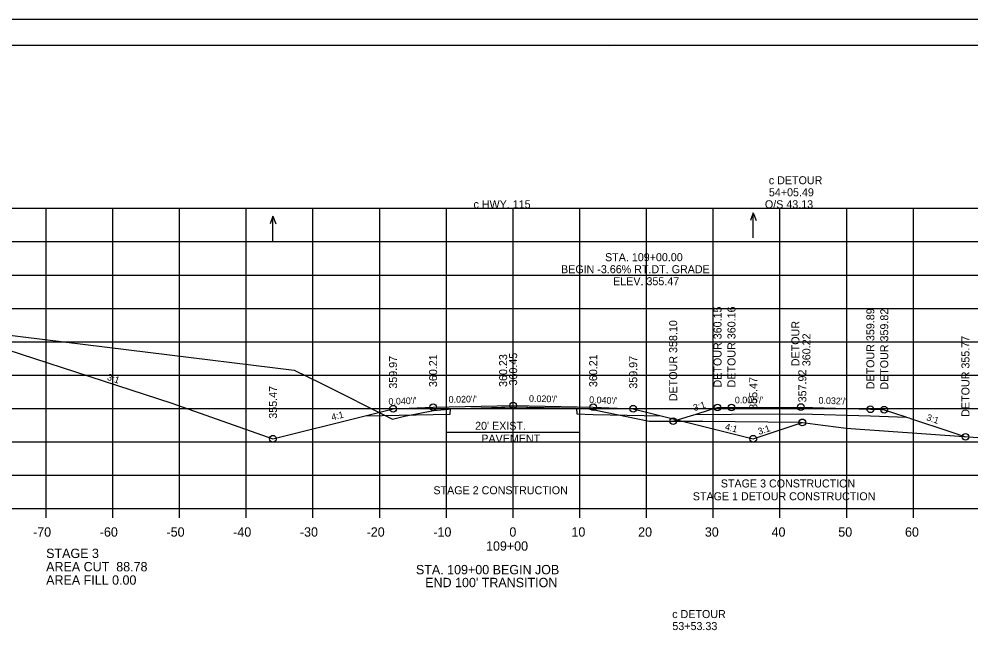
# Model space of a CAD drawing. Extents: x 1630712 to 1632516, y 782146 to 785403.
# Drawn here: x 1632258.9 to 1632401.6, y 783818.1 to 783910 of the extents above; entities that cross this region are included whole.
import ezdxf

# ---------------------------------------------------------------- set-up
doc = ezdxf.new("R2010")
doc.units = 0
for name, color, linetype in [('Notes', 7, 'Continuous'), ('R_Alt Surface', 7, 'Continuous'), ('R_Annot', 7, 'Continuous'), ('R_Axis', 7, 'Continuous'), ('R_Axis Annot', 7, 'Continuous'), ('R_Border', 7, 'Continuous'), ('R_Detour Subgrade', 7, 'Continuous'), ('R_Detour Surface', 7, 'Continuous'), ('R_Exist Surface', 7, 'Continuous'), ('R_Fin Surface', 7, 'Continuous'), ('R_Grid', 7, 'Continuous'), ('R_No Plot', 7, 'Continuous'), ('R_Water Annot', 7, 'Continuous'), ('R_Xsect Elev', 7, 'Continuous'), ('R_Xsect Elev Detour', 7, 'Continuous'), ('R_Xsect Slope', 7, 'Continuous')]:
    doc.layers.add(name, color=color, linetype=linetype)

msp = doc.modelspace()

# ---------------------------------------------------------------- linework, layer by layer
at = {"layer": 'Notes'}
for p, q in [((1632322.96, 783846.37), (1632322.96, 783849.77)), ((1632342.96, 783846.37), (1632342.96, 783849.77)), ((1632322.96, 783848.07), (1632342.96, 783848.07))]:
    msp.add_line(p, q, dxfattribs=at)
at = {"layer": 'R_Alt Surface'}
msp.add_lwpolyline([(1632310.79, 783850.54), (1632320.96, 783850.74), (1632323.5, 783850.79), (1632323.55, 783851.57), (1632332.75, 783851.85), (1632342.47, 783851.67), (1632342.52, 783850.8), (1632344.96, 783850.74), (1632355.14, 783850.54)], dxfattribs=at)
at = {"layer": 'R_Axis'}
for p, q in [((1632212.96, 783836.62), (1632492.96, 783836.62)), ((1632262.96, 783835.22), (1632262.96, 783836.62)), ((1632272.96, 783835.22), (1632272.96, 783836.62)), ((1632282.96, 783835.22), (1632282.96, 783836.62)), ((1632292.96, 783835.22), (1632292.96, 783836.62)), ((1632302.96, 783835.22), (1632302.96, 783836.62)), ((1632312.96, 783835.22), (1632312.96, 783836.62)), ((1632322.96, 783835.22), (1632322.96, 783836.62)), ((1632332.96, 783835.22), (1632332.96, 783836.62)), ((1632342.96, 783835.22), (1632342.96, 783836.62)), ((1632352.96, 783835.22), (1632352.96, 783836.62)), ((1632362.96, 783835.22), (1632362.96, 783836.62)), ((1632372.96, 783835.22), (1632372.96, 783836.62)), ((1632382.96, 783835.22), (1632382.96, 783836.62)), ((1632392.96, 783835.22), (1632392.96, 783836.62))]:
    msp.add_line(p, q, dxfattribs=at)
at = {"layer": 'R_Border'}
for p, q in [((1632194.96, 783906.08), (1632511.14, 783906.08)), ((1632347.48, 783905.82), (1632347.48, 783905.82)), ((1632347.48, 783905.82), (1632347.48, 783905.82))]:
    msp.add_line(p, q, dxfattribs=at)
at = {"layer": 'R_Detour Subgrade'}
msp.add_lwpolyline([(1632360.27, 783850.74), (1632365.69, 783850.78), (1632376.1, 783850.84), (1632386.51, 783850.5), (1632391.92, 783850.33)], dxfattribs=at)
at = {"layer": 'R_Detour Surface'}
msp.add_lwpolyline([(1632356.95, 783849.72), (1632359.72, 783850.57), (1632360.27, 783850.74), (1632362.56, 783851.45), (1632363.6, 783851.77), (1632364.8, 783851.77), (1632365.69, 783851.78), (1632376.1, 783851.84), (1632376.1, 783851.84), (1632376.1, 783851.84), (1632386.51, 783851.5), (1632388.05, 783851.45), (1632388.59, 783851.44), (1632391.82, 783850.36), (1632391.92, 783850.33), (1632391.93, 783850.32), (1632392.29, 783850.21), (1632392.54, 783850.12), (1632392.54, 783850.12), (1632398.58, 783848.11), (1632400.76, 783847.38)], dxfattribs=at)
at = {"layer": 'R_Exist Surface'}
msp.add_lwpolyline([(1632256.26, 783862.76), (1632300.13, 783857.36), (1632304.11, 783855.4), (1632314.86, 783850.04), (1632316.68, 783850.46), (1632321.04, 783851.33), (1632323.22, 783851.54), (1632323.55, 783851.57), (1632331.72, 783851.82), (1632332.75, 783851.85), (1632341.55, 783851.69), (1632342.47, 783851.67), (1632344.3, 783851.55), (1632344.76, 783851.52), (1632345.11, 783851.44), (1632353.35, 783849.74), (1632361.39, 783849.7), (1632375.97, 783849.58), (1632378.25, 783849.29), (1632382.87, 783848.65), (1632418.85, 783846.11)], dxfattribs=at)
at = {"layer": 'R_Fin Surface'}
msp.add_lwpolyline([(1632246.74, 783863.83), (1632281.81, 783852.44), (1632296.96, 783847.09), (1632310.79, 783850.54), (1632314.96, 783851.59), (1632320.96, 783851.83), (1632332.96, 783852.07), (1632344.96, 783851.83), (1632350.96, 783851.59), (1632355.14, 783850.54), (1632368.96, 783847.09), (1632368.96, 783847.09), (1632376.31, 783849.54)], dxfattribs=at)
at = {"layer": 'R_Grid'}
for p, q in [((1632212.96, 783881.62), (1632492.96, 783881.62)), ((1632262.96, 783836.62), (1632262.96, 783881.62)), ((1632272.96, 783836.62), (1632272.96, 783881.62)), ((1632282.96, 783836.62), (1632282.96, 783881.62)), ((1632292.96, 783836.62), (1632292.96, 783881.62)), ((1632302.96, 783836.62), (1632302.96, 783881.62)), ((1632312.96, 783836.62), (1632312.96, 783881.62)), ((1632322.96, 783836.62), (1632322.96, 783881.62)), ((1632332.96, 783836.62), (1632332.96, 783881.62)), ((1632342.96, 783836.62), (1632342.96, 783881.62)), ((1632352.96, 783836.62), (1632352.96, 783881.62)), ((1632362.96, 783836.62), (1632362.96, 783881.62)), ((1632372.96, 783836.62), (1632372.96, 783881.62)), ((1632382.96, 783836.62), (1632382.96, 783881.62)), ((1632392.96, 783836.62), (1632392.96, 783881.62)), ((1632212.96, 783876.62), (1632492.96, 783876.62)), ((1632212.96, 783871.62), (1632492.96, 783871.62)), ((1632212.96, 783866.62), (1632492.96, 783866.62)), ((1632212.96, 783861.62), (1632492.96, 783861.62)), ((1632212.96, 783856.62), (1632492.96, 783856.62)), ((1632212.96, 783851.62), (1632492.96, 783851.62)), ((1632212.96, 783846.62), (1632492.96, 783846.62)), ((1632212.96, 783841.62), (1632492.96, 783841.62)), ((1632212.96, 783836.62), (1632492.96, 783836.62))]:
    msp.add_line(p, q, dxfattribs=at)
at = {"layer": 'R_No Plot'}
msp.add_line((1632182.56, 783909.97), (1632515.9, 783909.97), dxfattribs=at)
msp.add_lwpolyline([(1632182.56, 783909.97), (1632515.9, 783909.97), (1632515.9, 783696.63), (1632182.56, 783696.63)], close=True, dxfattribs=at)
for centre in [(1632320.96, 783851.83), (1632332.96, 783852.07), (1632344.96, 783851.83), (1632363.6, 783851.77), (1632365.69, 783851.78), (1632376.1, 783851.84), (1632314.96, 783851.59), (1632350.96, 783851.59), (1632386.51, 783851.5), (1632388.59, 783851.44), (1632356.95, 783849.72), (1632376.31, 783849.54), (1632400.76, 783847.38), (1632296.96, 783847.09), (1632296.96, 783847.09), (1632368.96, 783847.09), (1632368.96, 783847.09)]:
    msp.add_circle(centre, 0.5, dxfattribs=at)
at = {"layer": 'R_Water Annot'}
for p, q in [((1632368.96, 783880.96), (1632368.54, 783879.81)), ((1632368.96, 783877.19), (1632368.96, 783880.96)), ((1632368.96, 783880.96), (1632369.38, 783879.81)), ((1632296.96, 783880.45), (1632296.54, 783879.29)), ((1632296.96, 783876.68), (1632296.96, 783880.45)), ((1632296.96, 783880.45), (1632297.38, 783879.29))]:
    msp.add_line(p, q, dxfattribs=at)

# ---------------------------------------------------------------- texts
at = {"layer": 'Notes'}
for s, p in [('c DETOUR', (1632371.29, 783885.22)), ('54+05.49', (1632371.3, 783883.42)), ('c HWY. 115', (1632327.02, 783881.62)), ('O/S 43.13', (1632370.7, 783881.62)), ('STA. 109+00.00', (1632346.74, 783873.69)), ('BEGIN -3.66% RT.DT. GRADE', (1632340.14, 783871.89)), ('ELEV. 355.47', (1632347.95, 783870.09)), ("20' EXIST.", (1632327.26, 783848.43)), ('PAVEMENT', (1632328.19, 783846.51)), ('STAGE 3 CONSTRUCTION', (1632364.09, 783839.79)), ('STAGE 2 CONSTRUCTION', (1632321.01, 783838.77)), ('STAGE 1 DETOUR CONSTRUCTION', (1632359.89, 783837.87)), ('c DETOUR', (1632356.81, 783820.22)), ('53+53.33', (1632356.83, 783818.42))]:
    msp.add_text(s, height=1.2, dxfattribs=at).set_placement(p)
at = {"layer": 'R_Annot'}
for s, p in [('STA. 109+00 BEGIN JOB', (1632318.39, 783826.78)), ("END 100' TRANSITION", (1632319.78, 783824.85))]:
    msp.add_text(s, height=1.4, dxfattribs=at).set_placement(p)
at = {"layer": 'R_Axis Annot'}
for s, p in [('-70', (1632261, 783832.42)), ('-60', (1632271, 783832.42)), ('-50', (1632281, 783832.42)), ('-40', (1632291, 783832.42)), ('-30', (1632301, 783832.42)), ('-20', (1632311, 783832.42)), ('-10', (1632321, 783832.42)), ('0', (1632332.4, 783832.42)), ('10', (1632341.7, 783832.42)), ('20', (1632351.7, 783832.42)), ('30', (1632361.7, 783832.42)), ('40', (1632371.7, 783832.42)), ('50', (1632381.7, 783832.42)), ('60', (1632391.7, 783832.42)), ('109+00', (1632328.9, 783830.32)), ('STAGE 3', (1632262.96, 783829.22)), ('AREA CUT  88.78', (1632262.96, 783827.22)), ('AREA FILL 0.00', (1632262.96, 783825.22))]:
    msp.add_text(s, height=1.4, dxfattribs=at).set_placement(p)
at = {"layer": 'R_Xsect Elev'}
for s, p in [('359.97', (1632315.56, 783854.59)), ('360.21', (1632321.56, 783854.83)), ('360.23', (1632332.06, 783854.85)), ('360.45', (1632333.56, 783855.07)), ('360.21', (1632345.56, 783854.83)), ('359.97', (1632351.56, 783854.59)), ('357.92', (1632376.91, 783852.54)), ('   355.47', (1632369.56, 783850.09)), ('355.47', (1632297.56, 783850.09))]:
    msp.add_text(s, height=1.2, rotation=90, dxfattribs=at).set_placement(p)
at = {"layer": 'R_Xsect Elev Detour'}
for s, p in [('DETOUR 360.15', (1632364.2, 783854.77)), ('DETOUR 360.16', (1632366.29, 783854.78)), ('DETOUR 359.89', (1632387.11, 783854.5)), ('DETOUR 359.82', (1632389.19, 783854.44)), ('DETOUR 358.10', (1632357.55, 783852.72)), ('       DETOUR', (1632375.87, 783854.84)), ('       360.22', (1632377.52, 783854.84)), ('DETOUR 355.77', (1632401.36, 783850.38))]:
    msp.add_text(s, height=1.2, rotation=90, dxfattribs=at).set_placement(p)
at = {"layer": 'R_Xsect Slope'}
for s, rotation, p in [('3:1', 341.5651, (1632272.01, 783855.93)), ("0.020'/'", 1.1458, (1632323.3, 783852.47)), ("0.020'/'", 358.8542, (1632335.33, 783852.62)), ("0.040'/'", 2.2906, (1632314.29, 783852.16)), ("0.040'/'", 357.7094, (1632344.34, 783852.45)), ('3:1', 17.0641, (1632360.13, 783851.22)), ("0.005'/'", 0.3354, (1632366.2, 783852.38)), ("0.032'/'", 358.1533, (1632378.72, 783852.35)), ('4:1', 14.0362, (1632305.84, 783849.82)), ('3:1', 341.5798, (1632394.83, 783849.88)), ('4:1', 345.9638, (1632364.65, 783848.45)), ('3:1', 18.435, (1632369.83, 783847.66))]:
    msp.add_text(s, height=1, rotation=rotation, dxfattribs=at).set_placement(p)

doc.saveas('drawing.dxf')
